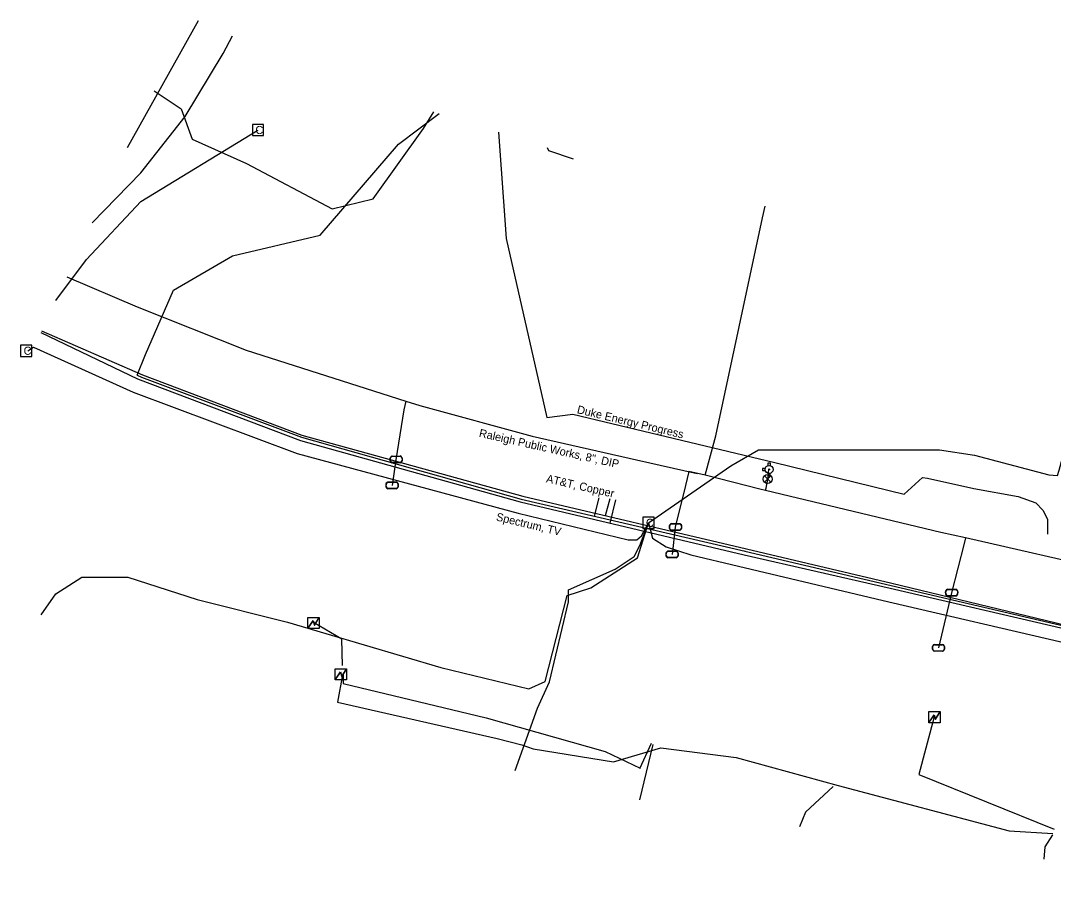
# Model space of a CAD drawing. Extents: x 2070721 to 2083340, y 729290 to 737883.
# Drawn here: x 2081558 to 2082068, y 736200 to 736623 of the extents above; entities that cross this region are included whole.
import ezdxf

# ---------------------------------------------------------------- set-up
doc = ezdxf.new("R2010")
doc.units = 0
for name, color, linetype in [('Exist Utilities Power Transformer CELL', 7, 'Continuous'), ('Exist Utilities Power UG Cable SUE LOS B', 7, 'Continuous'), ('Exist Utilities Power UG Cable SUE LOS B Text', 7, 'Continuous'), ('Exist Utilities Telephone UG Cable SUE LOS C', 7, 'Continuous'), ('Exist Utilities Telephone UG Cable SUE LOS C Leader', 7, 'Continuous'), ('Exist Utilities Telephone UG Cable SUE LOS C Text', 7, 'Continuous'), ('Exist Utilities TV Pedestal CELL', 7, 'Continuous'), ('Exist Utilities TV UG Cable SUE LOS C', 7, 'Continuous'), ('Exist Utilities TV UG Cable SUE LOS C Text', 7, 'Continuous'), ('Exist Utilities Water Fire Hydrant CELL', 7, 'Continuous'), ('Exist Utilities Water Meter CELL', 7, 'Continuous'), ('Exist Utilities Water UG Line SUE LOS B', 7, 'Continuous'), ('Exist Utilities Water UG Line SUE LOS B Text', 7, 'Continuous'), ('Exist Utilities Water Valve CELL', 7, 'Continuous')]:
    doc.layers.add(name, color=color, linetype=linetype)

msp = doc.modelspace()

# ---------------------------------------------------------------- linework, layer by layer
at = {"layer": 'Exist Utilities Power Transformer CELL'}
for p, q in [((2081702.7, 736325.61), (2081702.7, 736325.61)), ((2081716.19, 736300.27), (2081716.19, 736300.27)), ((2082009, 736279.19), (2082009, 736279.19))]:
    msp.add_line(p, q, dxfattribs=at)
for points in [[(2081699.86, 736328.22), (2081705.41, 736328.22), (2081705.41, 736322.67), (2081699.86, 736322.67)], [(2081713.35, 736302.88), (2081718.9, 736302.88), (2081718.9, 736297.33), (2081713.35, 736297.33)], [(2082006.16, 736281.8), (2082011.71, 736281.8), (2082011.71, 736276.25), (2082006.16, 736276.25)]]:
    msp.add_lwpolyline(points, close=True, dxfattribs=at)
for points in [[(2081699.86, 736322.67), (2081702.5, 736326.61), (2081703.13, 736324.4), (2081705.41, 736328.22)], [(2081699.93, 736322.67), (2081702.5, 736326.4), (2081703.09, 736324.22), (2081705.41, 736328.07)], [(2081713.35, 736297.33), (2081715.99, 736301.27), (2081716.62, 736299.06), (2081718.9, 736302.88)], [(2081713.42, 736297.33), (2081715.99, 736301.06), (2081716.58, 736298.88), (2081718.9, 736302.73)], [(2082006.16, 736276.25), (2082008.8, 736280.19), (2082009.43, 736277.98), (2082011.71, 736281.8)], [(2082006.23, 736276.25), (2082008.8, 736279.98), (2082009.39, 736277.8), (2082011.71, 736281.65)]]:
    msp.add_lwpolyline(points, dxfattribs=at)
at = {"layer": 'Exist Utilities Power UG Cable SUE LOS B'}
msp.add_line((2081869.95, 736265.5), (2081863.38, 736238.25), dxfattribs=at)
for points in [[(2081593.51, 736522.9), (2081617.43, 736547.49), (2081639.43, 736575.38), (2081658.05, 736606.46), (2081662.69, 736615.09)], [(2081624.06, 736588.07), (2081637.35, 736579.12), (2081642.78, 736564.1), (2081669.56, 736552.07), (2081711.84, 736529.72), (2081732.02, 736534.7), (2081756.88, 736569.41), (2081762.09, 736577.62)], [(2081793.97, 736567.61), (2081797.64, 736515.06), (2081817.81, 736426.78), (2081830.54, 736428.4), (2081868.97, 736419.19), (2081930.14, 736404.7), (2081994.03, 736388.95), (2082003.1, 736397.16), (2082005.52, 736396.93)], [(2081817.86, 736560.12), (2081818.61, 736558.64), (2081830.67, 736554.47)], [(2082005.52, 736396.93), (2082028.31, 736391.85), (2082050.28, 736387.92)], [(2082050.28, 736387.92), (2082058.9, 736384.67), (2082062.45, 736381.12), (2082064.71, 736376.6), (2082064.71, 736369.34)], [(2081716.95, 736304.41), (2081716.62, 736317.49), (2081702.59, 736325.64)], [(2081716.93, 736299.92), (2081714.46, 736286.45), (2081793.21, 736268.43), (2081805.43, 736265.26), (2081810.95, 736263.37)], [(2081717.34, 736300.03), (2081717.21, 736295.55), (2081787.8, 736278.61), (2081846.5, 736261.98), (2081863.85, 736253.78), (2081863.67, 736253.65), (2081869.34, 736266.08)], [(2082008.8, 736279.06), (2082001.18, 736250.65), (2082068.04, 736223.8)], [(2081810.95, 736263.37), (2081850.56, 736256.87), (2081874.02, 736263.85), (2081911.12, 736259.04), (2081961.37, 736245.31), (2082045.75, 736222.88), (2082067.35, 736221.62)], [(2081958.92, 736244.7), (2081945.38, 736232.03), (2081942.33, 736224.89)], [(2082067.1, 736220.9), (2082063.38, 736215.05), (2082062.82, 736208.84)]]:
    msp.add_lwpolyline(points, dxfattribs=at)
at = {"layer": 'Exist Utilities Telephone UG Cable SUE LOS C'}
for points in [[(2081615.72, 736447.72), (2081619.87, 736457.87), (2081633.54, 736489.64), (2081662.78, 736506.59), (2081706.01, 736516.81), (2081744.57, 736561.71), (2081764.57, 736576.83)], [(2081568.17, 736468.83), (2081615.92, 736445.96), (2081696.31, 736415.49), (2081804.57, 736385.24), (2081915.03, 736359.08), (2081987.17, 736342.62), (2082073.48, 736322.55), (2082138.89, 736307.01), (2082220.41, 736288.62), (2082293.92, 736270.7)], [(2081568.48, 736469.51), (2081618.39, 736447.85), (2081696.88, 736418.07), (2081805.87, 736388.07), (2081916.17, 736362.01), (2081987.94, 736345.05), (2082073.78, 736324.33), (2082139.32, 736308.59), (2082221.63, 736291.02), (2082296.5, 736270.5)], [(2081615.72, 736447.72), (2081617.75, 736446.75), (2081696.77, 736417.12), (2081805.08, 736386.54), (2081915.58, 736360.92), (2081915.48, 736360.89), (2081987.51, 736343.92), (2082073.49, 736323.81), (2082139.92, 736308.03), (2082220.81, 736289.54), (2082294.45, 736271.08)]]:
    msp.add_lwpolyline(points, dxfattribs=at)
at = {"layer": 'Exist Utilities Telephone UG Cable SUE LOS C Leader'}
for p, q in [((2081841.3, 736378.17), (2081843.56, 736387.2)), ((2081846.72, 736378.45), (2081848.94, 736386.91)), ((2081848.99, 736374.72), (2081851.73, 736386.2))]:
    msp.add_line(p, q, dxfattribs=at)
at = {"layer": 'Exist Utilities TV Pedestal CELL'}
for p, q in [((2081675.3, 736568.67), (2081675.3, 736568.67)), ((2081560.99, 736459.77), (2081560.99, 736459.77)), ((2081867.92, 736374.85), (2081867.92, 736374.85))]:
    msp.add_line(p, q, dxfattribs=at)
for points in [[(2081672.53, 736565.9), (2081678.07, 736565.9), (2081678.07, 736571.45), (2081672.53, 736571.45), (2081672.53, 736565.9)], [(2081558.22, 736456.99), (2081563.77, 736456.99), (2081563.77, 736462.55), (2081558.22, 736462.55), (2081558.22, 736456.99)], [(2081865.15, 736372.08), (2081870.7, 736372.08), (2081870.7, 736377.62), (2081865.15, 736377.62), (2081865.15, 736372.08)]]:
    msp.add_lwpolyline(points, dxfattribs=at)
at = {"layer": 'Exist Utilities TV UG Cable SUE LOS C'}
for points in [[(2081575.5, 736484.47), (2081590.65, 736504.86), (2081617.46, 736533.4), (2081675.12, 736568.6)], [(2081561.77, 736459.66), (2081564.51, 736461.5), (2081613.71, 736439.34), (2081694.53, 736409.12), (2081803.54, 736379.56), (2081857.88, 736366.5), (2081862.11, 736366.5), (2081864.43, 736368.45), (2081867.92, 736374.85)], [(2081867.92, 736374.85), (2081908.54, 736402.92), (2081922.2, 736410.85), (2081955.72, 736410.85), (2081976.56, 736410.85), (2082011.49, 736410.85), (2082028.68, 736408.17), (2082065.29, 736398.47), (2082069.56, 736398.28), (2082070.52, 736400.88), (2082075.6, 736419.83), (2082081.77, 736427.24), (2082099.8, 736423.88), (2082126.06, 736418.32), (2082170.39, 736408.66), (2082225.96, 736394.95), (2082242.36, 736398.41), (2082249.96, 736397.77)], [(2081568.39, 736329.45), (2081575.55, 736339.8), (2081588.34, 736348.06), (2081611.08, 736348.06), (2081645.32, 736337.04), (2081689.76, 736325.78), (2081765.44, 736303.46), (2081808.94, 736292.9), (2081816.89, 736296.62), (2081827.8, 736339.07), (2081839.46, 736342.78), (2081862.53, 736357.65), (2081867.92, 736374.85)], [(2081802.09, 736252.59), (2081813.22, 736283.38), (2081819.12, 736296.34), (2081828.46, 736335.85), (2081828.46, 736341.85), (2081851.47, 736352.07), (2081860.9, 736358.31), (2081863.63, 736363.74), (2081867.92, 736374.85)], [(2081867.92, 736374.85), (2081869.92, 736367.25), (2081876.67, 736362.95), (2081888.78, 736359.07), (2081912.22, 736353.44), (2081986.37, 736335.81), (2082072.78, 736315.77), (2082135.75, 736299.21), (2082217.86, 736275.92), (2082262.9, 736250.17), (2082262.99, 736250.08), (2082292.59, 736221.95), (2082307.6, 736199.94)]]:
    msp.add_lwpolyline(points, dxfattribs=at)
at = {"layer": 'Exist Utilities Water Fire Hydrant CELL'}
msp.add_line((2081927.4, 736401.2), (2081927.4, 736401.2), dxfattribs=at)
for points in [[(2081925.49, 736401.71), (2081924.2, 736401.71), (2081924.2, 736400.69), (2081925.49, 736400.69)], [(2081926.89, 736403.11), (2081926.89, 736404.4), (2081927.91, 736404.4), (2081927.91, 736403.09)], [(2081926.89, 736399.29), (2081926.89, 736398), (2081927.91, 736398), (2081927.91, 736399.31)]]:
    msp.add_lwpolyline(points, dxfattribs=at)
for radius in [1.98, 0.243]:
    msp.add_circle((2081927.4, 736401.2), radius, dxfattribs=at)
at = {"layer": 'Exist Utilities Water Meter CELL'}
for p, q in [((2081743.45, 736406.13), (2081743.45, 736406.13)), ((2081741.43, 736393.35), (2081741.43, 736393.35)), ((2081881.24, 736372.78), (2081881.24, 736372.78)), ((2081879.54, 736359.27), (2081879.54, 736359.27)), ((2082017.46, 736340.42), (2082017.46, 736340.42)), ((2082010.93, 736313.18), (2082010.93, 736313.18))]:
    msp.add_line(p, q, dxfattribs=at)
for points in [[(2081741.41, 736407.83), (2081745.49, 736407.83)], [(2081741.41, 736407.69), (2081745.49, 736407.69)], [(2081745.49, 736404.57), (2081741.39, 736404.57)], [(2081745.49, 736404.43), (2081741.39, 736404.43)], [(2081743.47, 736391.79), (2081739.37, 736391.79)], [(2081743.47, 736391.65), (2081739.37, 736391.65)], [(2081739.39, 736395.05), (2081743.47, 736395.05)], [(2081739.39, 736394.91), (2081743.47, 736394.91)], [(2081883.28, 736371.22), (2081879.18, 736371.22)], [(2081883.28, 736371.08), (2081879.18, 736371.08)], [(2081879.2, 736374.48), (2081883.28, 736374.48)], [(2081879.2, 736374.34), (2081883.28, 736374.34)], [(2081877.5, 736360.97), (2081881.58, 736360.97)], [(2081881.58, 736357.71), (2081877.48, 736357.71)], [(2081881.58, 736357.57), (2081877.48, 736357.57)], [(2081877.5, 736360.83), (2081881.58, 736360.83)], [(2082015.42, 736342.12), (2082019.5, 736342.12)], [(2082015.42, 736341.98), (2082019.5, 736341.98)], [(2082019.5, 736338.86), (2082015.4, 736338.86)], [(2082019.5, 736338.72), (2082015.4, 736338.72)], [(2082012.97, 736311.62), (2082008.87, 736311.62)], [(2082012.97, 736311.48), (2082008.87, 736311.48)], [(2082008.89, 736314.88), (2082012.97, 736314.88)], [(2082008.89, 736314.74), (2082012.97, 736314.74)]]:
    msp.add_lwpolyline(points, dxfattribs=at)
for centre, radius, start, end in [((2081742.14, 736406.12), 1.86, 113.178, 245.9794), ((2081742.15, 736406.12), 1.73, 115.3009, 243.7824), ((2081744.74, 736406.13), 1.86, 293.6483, 66.3084), ((2081744.75, 736406.13), 1.73, 295.1272, 64.8728), ((2081740.12, 736393.34), 1.86, 113.178, 245.9794), ((2081740.13, 736393.34), 1.73, 115.3009, 243.7824), ((2081742.72, 736393.35), 1.86, 293.6483, 66.3084), ((2081742.73, 736393.35), 1.73, 295.1272, 64.8728), ((2081879.93, 736372.77), 1.86, 113.178, 245.9794), ((2081879.94, 736372.77), 1.73, 115.3009, 243.7824), ((2081882.53, 736372.78), 1.86, 293.6483, 66.3084), ((2081882.54, 736372.78), 1.73, 295.1272, 64.8728), ((2081878.23, 736359.26), 1.86, 113.178, 245.9794), ((2081880.83, 736359.27), 1.86, 293.6483, 66.3084), ((2081878.24, 736359.26), 1.73, 115.3009, 243.7824), ((2081880.84, 736359.27), 1.73, 295.1272, 64.8728), ((2082016.15, 736340.41), 1.86, 113.178, 245.9794), ((2082016.16, 736340.41), 1.73, 115.3009, 243.7824), ((2082018.75, 736340.42), 1.86, 293.6483, 66.3084), ((2082018.76, 736340.42), 1.73, 295.1272, 64.8728), ((2082009.62, 736313.17), 1.86, 113.178, 245.9794), ((2082009.63, 736313.17), 1.73, 115.3009, 243.7824), ((2082012.22, 736313.18), 1.86, 293.6483, 66.3084), ((2082012.23, 736313.18), 1.73, 295.1272, 64.8728)]:
    msp.add_arc(centre, radius, start, end, dxfattribs=at)
at = {"layer": 'Exist Utilities Water UG Line SUE LOS B'}
for points in [[(2081610.89, 736559.97), (2081646, 736622.62)], [(2081895.92, 736398.39), (2081898.48, 736408.05), (2081901.09, 736417.77), (2081924.13, 736525.36), (2081925.42, 736531.03)], [(2081581.04, 736496.29), (2081615.73, 736481.45), (2081669.42, 736460.1), (2081748.23, 736434.96)], [(2081748.23, 736434.96), (2081747.28, 736430.58), (2081743.34, 736405.99), (2081741.41, 736393.34)], [(2081748.23, 736434.96), (2081755.16, 736432.79), (2081810.5, 736417.55), (2081861.99, 736405.96), (2081891.89, 736399.27)], [(2081887.85, 736400.15), (2081886.16, 736393.27), (2081881.11, 736372.66), (2081879.62, 736359.28)], [(2081895.92, 736398.39), (2081887.85, 736400.15)], [(2081925.63, 736390.78), (2081922.81, 736391.44), (2081895.86, 736398.32)], [(2081925.63, 736390.78), (2081925.87, 736392.04), (2081926.72, 736396.45), (2081927.31, 736401.22)], [(2082024.3, 736367.53), (2082012.08, 736370.04), (2081925.63, 736390.78)], [(2082024.3, 736367.53), (2082023.59, 736364.74), (2082017.34, 736340.25), (2082011.01, 736313.15)], [(2082096.13, 736351.01), (2082024.3, 736367.53)]]:
    msp.add_lwpolyline(points, dxfattribs=at)
at = {"layer": 'Exist Utilities Water Valve CELL'}
msp.add_lwpolyline([(2081928.26, 736398.02), (2081925.1, 736394.86), (2081926.68, 736396.44), (2081928.26, 736394.86), (2081925.1, 736398.02)], dxfattribs=at)
msp.add_circle((2081926.68, 736396.44), 2.23, dxfattribs=at)

# ---------------------------------------------------------------- texts
at = {"layer": 'Exist Utilities Power UG Cable SUE LOS B Text'}
msp.add_text('Duke Energy Progress', height=4, rotation=346.5229, dxfattribs=at).set_placement((2081832.36, 736429.01))
at = {"layer": 'Exist Utilities Telephone UG Cable SUE LOS C Text'}
msp.add_text('AT&T, Copper', height=4, rotation=347.1366, dxfattribs=at).set_placement((2081817.17, 736394.89))
at = {"layer": 'Exist Utilities TV Pedestal CELL'}
for p in [(2081673.99, 736566.67), (2081559.68, 736457.77), (2081866.61, 736372.85)]:
    msp.add_text('C', height=4, dxfattribs=at).set_placement(p)
at = {"layer": 'Exist Utilities TV UG Cable SUE LOS C Text'}
msp.add_text('Spectrum, TV', height=4, rotation=346.4859, dxfattribs=at).set_placement((2081792.45, 736376.06))
at = {"layer": 'Exist Utilities Water UG Line SUE LOS B Text'}
msp.add_text('Raleigh Public Works, 8", DIP ', height=4, rotation=347.3117, dxfattribs=at).set_placement((2081784.04, 736417.36))

doc.saveas('drawing.dxf')
